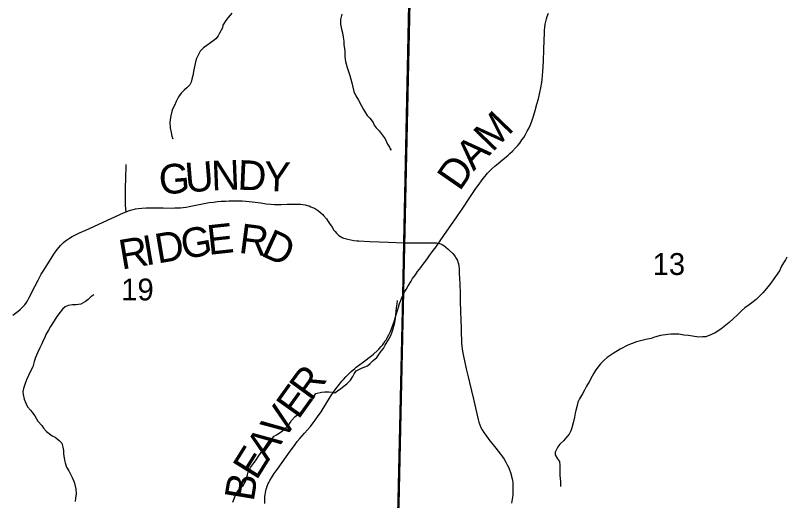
# Model space of a CAD drawing. Extents: x -7.1 to 34, y 0 to 22.
# Drawn here: x 5.914 to 7.392, y 14.742 to 15.673 of the extents above; entities that cross this region are included whole.
import ezdxf

# ---------------------------------------------------------------- set-up
doc = ezdxf.new("R2010")
doc.units = 0
for name, color, linetype in [('GM_X_County_Road', 7, 'Continuous'), ('GM_X_County_Road_Text', 7, 'Continuous'), ('GM_X_Minor_River', 7, 'Continuous'), ('GM_X_Section', 7, 'Continuous'), ('GM_X_Section_Text', 7, 'Continuous'), ('GM_X_Township_Road', 7, 'Continuous')]:
    doc.layers.add(name, color=color, linetype=linetype)

msp = doc.modelspace()

# ---------------------------------------------------------------- linework, layer by layer
at = {"layer": 'GM_X_County_Road'}
for points in [[(6.7252, 15.2358), (6.7271, 15.2386), (6.7366, 15.2523), (6.753, 15.2761), (6.7616, 15.2883), (6.7702, 15.3011), (6.7851, 15.3236), (6.7953, 15.3388), (6.8039, 15.3511), (6.8107, 15.3601), (6.8141, 15.3645), (6.8192, 15.3703), (6.8222, 15.3736), (6.8273, 15.3786), (6.833, 15.3836), (6.8391, 15.3887), (6.8475, 15.3955), (6.8583, 15.4046), (6.8617, 15.4076), (6.8668, 15.4124), (6.8728, 15.4186), (6.8768, 15.423), (6.8809, 15.4279), (6.885, 15.4338), (6.8884, 15.4388), (6.8918, 15.4444), (6.8952, 15.4504), (6.8986, 15.4573), (6.9006, 15.4617), (6.9038, 15.4699), (6.9071, 15.4795), (6.9104, 15.4902), (6.9137, 15.5024), (6.9163, 15.5126), (6.9192, 15.5249), (6.9211, 15.5339), (6.9228, 15.5439), (6.9234, 15.5497), (6.9243, 15.5575), (6.9251, 15.5654), (6.9261, 15.5848), (6.927, 15.608), (6.9281, 15.6396), (6.9284, 15.6438), (6.9288, 15.6499), (6.9295, 15.6557), (6.9307, 15.6611), (6.9319, 15.6661), (6.9334, 15.6708), (6.9355, 15.6767)], [(5.9091, 15.098), (5.9144, 15.1016), (5.9194, 15.1053), (5.9234, 15.1085), (5.9262, 15.1112), (5.9287, 15.1139), (5.9323, 15.1178), (5.9352, 15.1219), (5.9379, 15.1264), (5.94, 15.1305), (5.9515, 15.1527), (5.9576, 15.1646), (5.9639, 15.1762), (5.9685, 15.1838), (5.975, 15.1942), (5.9825, 15.2063), (5.9878, 15.2145), (5.9941, 15.2234), (5.9978, 15.2281), (6.0004, 15.2311), (6.0034, 15.2342), (6.0063, 15.237), (6.0103, 15.2403), (6.0138, 15.2429), (6.0181, 15.2456), (6.0231, 15.2485), (6.0304, 15.2523), (6.0373, 15.2555), (6.0492, 15.261), (6.0979, 15.2833), (6.1214, 15.2938), (6.1265, 15.2959), (6.1311, 15.2978), (6.1349, 15.2992), (6.1399, 15.3006), (6.1445, 15.3016), (6.1499, 15.3024), (6.1568, 15.3031), (6.1651, 15.3035), (6.1695, 15.3036), (6.1976, 15.3034), (6.2138, 15.3032), (6.2196, 15.3033), (6.2307, 15.3038), (6.236, 15.3044), (6.2413, 15.3051), (6.247, 15.306), (6.2727, 15.3114), (6.2858, 15.3137), (6.2938, 15.3147), (6.3014, 15.3156), (6.3088, 15.3162), (6.3167, 15.3166), (6.324, 15.317), (6.3305, 15.3171), (6.3429, 15.317), (6.3489, 15.3168), (6.3556, 15.3163), (6.3684, 15.3151), (6.3739, 15.3145), (6.3847, 15.313), (6.3946, 15.3115), (6.4037, 15.3105), (6.4106, 15.3101), (6.4158, 15.31), (6.4238, 15.3101), (6.4353, 15.3106), (6.4431, 15.3109), (6.4562, 15.3107), (6.4606, 15.3105), (6.4648, 15.31), (6.4694, 15.3093), (6.4734, 15.3083), (6.477, 15.3072), (6.4806, 15.3058), (6.4836, 15.3045), (6.4871, 15.3028), (6.4909, 15.3005), (6.495, 15.2976), (6.5001, 15.2935), (6.5033, 15.2907), (6.5046, 15.2892), (6.5101, 15.2826), (6.5126, 15.2792), (6.5164, 15.2735), (6.521, 15.2666), (6.5247, 15.261), (6.5269, 15.258), (6.5293, 15.2553), (6.5317, 15.253), (6.5343, 15.2508), (6.5374, 15.2487), (6.5404, 15.247), (6.5431, 15.2457), (6.5459, 15.2447), (6.5515, 15.2432), (6.5571, 15.242), (6.5627, 15.2411), (6.5687, 15.2405), (6.5723, 15.2402), (6.5936, 15.2391), (6.6292, 15.2376), (6.6589, 15.2366), (6.6647, 15.2364)], [(6.6628, 15.1472), (6.667, 15.1543), (6.6723, 15.1628), (6.6754, 15.1678), (6.6806, 15.1752), (6.685, 15.1813), (6.6911, 15.1894), (6.6956, 15.1954), (6.7006, 15.2021), (6.704, 15.2066), (6.708, 15.2121), (6.7116, 15.217), (6.7148, 15.2216), (6.7183, 15.2264), (6.7225, 15.2321), (6.7252, 15.2358)], [(6.6647, 15.2364), (6.7016, 15.2365), (6.7174, 15.2367), (6.7193, 15.2366), (6.7214, 15.2364), (6.7239, 15.236), (6.7252, 15.2358), (6.7269, 15.2354), (6.7291, 15.2347), (6.731, 15.2339), (6.7327, 15.2329), (6.7343, 15.2318), (6.7434, 15.2241), (6.746, 15.2218), (6.7522, 15.2158), (6.7544, 15.2133), (6.7569, 15.2102), (6.7585, 15.2078), (6.7598, 15.2055), (6.7611, 15.2028), (6.7623, 15.1996), (6.7633, 15.1959), (6.7638, 15.1919), (6.7643, 15.1866), (6.7647, 15.1785), (6.7656, 15.1576), (6.7664, 15.1399), (6.7668, 15.1247), (6.7673, 15.1049), (6.7678, 15.0881), (6.7683, 15.0724), (6.7687, 15.0613), (6.769, 15.0518), (6.7692, 15.044), (6.7697, 15.0386), (6.7702, 15.0333), (6.7716, 15.025), (6.7747, 15.0099), (6.7781, 14.9945), (6.7816, 14.9796), (6.7843, 14.9685), (6.7918, 14.9367), (6.8009, 14.8975), (6.8025, 14.8924), (6.8043, 14.8872), (6.8064, 14.8823), (6.8089, 14.8775), (6.8119, 14.8727), (6.8156, 14.8673), (6.8217, 14.8595), (6.8351, 14.8426), (6.8439, 14.8312), (6.8476, 14.8261), (6.8509, 14.8213), (6.854, 14.8159), (6.8566, 14.8109), (6.8589, 14.8061), (6.8601, 14.8033), (6.8634, 14.7943), (6.8644, 14.791), (6.8662, 14.7841), (6.8669, 14.7807), (6.8673, 14.7771), (6.8677, 14.7721), (6.8676, 14.7601), (6.8672, 14.7527), (6.8663, 14.7448), (6.865, 14.7371)], [(6.4972, 14.9078), (6.5, 14.9122), (6.5181, 14.9419), (6.5206, 14.9457), (6.5281, 14.9564), (6.5307, 14.9598), (6.54, 14.9713), (6.5427, 14.9744), (6.5474, 14.9793), (6.5521, 14.984), (6.5579, 14.9896), (6.5648, 14.9956), (6.5673, 14.9977), (6.574, 15.0028), (6.5814, 15.0085), (6.5971, 15.0202), (6.6004, 15.0229), (6.6083, 15.03), (6.6108, 15.0326), (6.6154, 15.0378), (6.6175, 15.0403), (6.6201, 15.044), (6.6231, 15.0483), (6.6245, 15.0505), (6.6268, 15.0545), (6.6296, 15.0598), (6.6329, 15.0667), (6.6358, 15.0736), (6.6376, 15.0787), (6.6399, 15.0854), (6.6419, 15.092), (6.6445, 15.1011), (6.6463, 15.107), (6.6483, 15.1134), (6.6505, 15.1201), (6.6526, 15.1261), (6.6539, 15.1296), (6.6553, 15.1329), (6.6579, 15.138), (6.6607, 15.1432), (6.6628, 15.1472)], [(6.392, 14.7368), (6.3922, 14.7438), (6.3925, 14.7512), (6.3927, 14.7526), (6.3934, 14.7578), (6.3948, 14.7639), (6.3952, 14.7653), (6.3967, 14.77), (6.3988, 14.7751), (6.3997, 14.7769), (6.4017, 14.7806), (6.4047, 14.7855), (6.4102, 14.7938), (6.4176, 14.8045), (6.4407, 14.8369), (6.4488, 14.8478), (6.4544, 14.8554), (6.459, 14.8611), (6.468, 14.8714), (6.4794, 14.8844), (6.485, 14.8913), (6.4889, 14.8964), (6.4966, 14.9069), (6.4972, 14.9078)]]:
    msp.add_lwpolyline(points, dxfattribs=at)
at = {"layer": 'GM_X_Minor_River'}
for points in [[(6.3217, 15.6687), (6.3172, 15.6629), (6.312, 15.6537), (6.311, 15.6487), (6.3051, 15.6388), (6.3029, 15.6334), (6.298, 15.628), (6.2928, 15.6233), (6.2879, 15.6198), (6.2808, 15.6148), (6.2744, 15.6105), (6.2681, 15.6039), (6.2637, 15.5951), (6.2607, 15.589), (6.259, 15.5802), (6.2561, 15.568), (6.2544, 15.5577), (6.2526, 15.5504), (6.2511, 15.5447), (6.2482, 15.5393), (6.243, 15.5335), (6.2374, 15.5296), (6.2318, 15.5238), (6.2269, 15.5162), (6.2222, 15.5073), (6.2192, 15.5), (6.2155, 15.4931), (6.2141, 15.4882), (6.212, 15.4798), (6.2109, 15.4729), (6.2099, 15.4676), (6.2108, 15.4573), (6.2124, 15.4482), (6.214, 15.4413), (6.2156, 15.436), (6.216, 15.4368)], [(6.3291, 15.6768), (6.3217, 15.6687)], [(6.5396, 15.6751), (6.5375, 15.6647), (6.5373, 15.6556), (6.5393, 15.6461), (6.5409, 15.6393), (6.5426, 15.6309), (6.5434, 15.6233), (6.5439, 15.6161), (6.5448, 15.6093), (6.5452, 15.6036), (6.5457, 15.5937), (6.547, 15.5842), (6.5498, 15.5728), (6.555, 15.5573), (6.559, 15.5436), (6.563, 15.527), (6.5669, 15.5186), (6.5716, 15.5103), (6.5774, 15.4994), (6.5813, 15.4922), (6.5852, 15.4858), (6.5883, 15.4805), (6.5933, 15.4757), (6.5998, 15.4674), (6.6018, 15.4621), (6.6053, 15.4572), (6.6111, 15.4512), (6.6153, 15.4459), (6.6192, 15.441), (6.6226, 15.4358), (6.6273, 15.4259), (6.6308, 15.4199), (6.6336, 15.4142), (6.6344, 15.4169)], [(7.3923, 15.2089), (7.3897, 15.2039), (7.3864, 15.1981), (7.3823, 15.1916), (7.3783, 15.1828), (7.3709, 15.172), (7.3597, 15.1566), (7.3463, 15.1404), (7.3404, 15.1339), (7.3336, 15.1277), (7.328, 15.123), (7.3202, 15.1176), (7.3123, 15.1117), (7.3059, 15.1059), (7.2981, 15.0982), (7.2817, 15.0835), (7.2663, 15.0707), (7.2554, 15.064), (7.2483, 15.0605), (7.237, 15.0565), (7.2309, 15.0561), (7.2241, 15.0556), (7.2116, 15.0573), (7.204, 15.0587), (7.1953, 15.0597), (7.1854, 15.0611), (7.1801, 15.0614), (7.1703, 15.0612), (7.1646, 15.0604), (7.1503, 15.0586), (7.1386, 15.0554), (7.1322, 15.053), (7.122, 15.0513), (7.1148, 15.0493), (7.1042, 15.0469), (7.0877, 15.0402), (7.073, 15.0327), (7.0595, 15.0245), (7.0483, 15.0163), (7.0427, 15.0117)], [(6.0644, 15.1365), (6.0588, 15.133), (6.0535, 15.1276), (6.0483, 15.1237), (6.0396, 15.119), (6.0306, 15.1177), (6.0238, 15.1176), (6.0155, 15.116), (6.0094, 15.114), (6.0046, 15.1093), (6.0001, 15.1032), (5.9934, 15.0951), (5.9886, 15.0866), (5.9812, 15.0762), (5.9775, 15.0689), (5.9727, 15.0609), (5.9705, 15.0548), (5.9676, 15.0494), (5.9647, 15.0425), (5.961, 15.0348), (5.9566, 15.0252), (5.9529, 15.0168), (5.9504, 15.0088), (5.9479, 14.9988), (5.9427, 14.9889), (5.9394, 14.982), (5.9358, 14.9735), (5.9321, 14.9647), (5.9296, 14.9571), (5.9285, 14.951), (5.929, 14.9453), (5.931, 14.9369), (5.9341, 14.929), (5.9376, 14.9222), (5.943, 14.9154), (5.9473, 14.9101), (5.9512, 14.9045), (5.957, 14.8947), (5.9647, 14.8861), (5.9678, 14.8808), (5.9739, 14.8748), (5.9846, 14.8662), (5.9907, 14.864), (5.9984, 14.8576), (6.0034, 14.852), (6.005, 14.8448), (6.0063, 14.8383), (6.0067, 14.8319), (6.0084, 14.8197), (6.0096, 14.8148), (6.012, 14.8064), (6.0163, 14.7989), (6.0206, 14.7917), (6.0233, 14.7864), (6.0253, 14.7804), (6.0276, 14.7755), (6.0301, 14.7641), (6.0306, 14.7553), (6.0295, 14.747), (6.0289, 14.7405)], [(6.331, 14.739), (6.3361, 14.7527), (6.3406, 14.7604), (6.3454, 14.767), (6.351, 14.7712), (6.3551, 14.7789), (6.359, 14.7915), (6.3605, 14.7969), (6.3645, 14.8053), (6.3705, 14.8134), (6.3757, 14.8203), (6.3816, 14.8292), (6.3875, 14.8373), (6.3924, 14.8438), (6.3961, 14.8499), (6.4001, 14.8553), (6.4054, 14.8607), (6.4098, 14.8658), (6.4147, 14.8685), (6.4218, 14.8728), (6.4293, 14.8782), (6.4372, 14.886), (6.4409, 14.891), (6.4435, 14.896), (6.4506, 14.9033), (6.4562, 14.9076), (6.461, 14.9115), (6.4674, 14.9161), (6.4734, 14.9234), (6.4793, 14.9296), (6.4823, 14.9354), (6.486, 14.9419), (6.49, 14.9473), (6.5006, 14.9501), (6.5074, 14.9506), (6.515, 14.9507), (6.5214, 14.9501), (6.5264, 14.949), (6.5312, 14.9529), (6.5376, 14.9568), (6.5492, 14.9661), (6.5563, 14.973), (6.5611, 14.98), (6.5637, 14.985), (6.5674, 14.9911), (6.5776, 14.9962), (6.5888, 15.0006), (6.5941, 15.0052), (6.6001, 15.011), (6.6068, 15.0164), (6.6105, 15.0226), (6.6149, 15.0284), (6.6194, 15.0338), (6.6231, 15.0403), (6.6301, 15.0514), (6.6331, 15.0576), (6.6353, 15.0637), (6.6378, 15.0698), (6.641, 15.0836), (6.6428, 15.0916), (6.6435, 15.0977), (6.6441, 15.1046), (6.6448, 15.1118), (6.6458, 15.1194), (6.6465, 15.1259)], [(7.0427, 15.0117), (7.0356, 15.0047), (7.0263, 14.9928), (7.0226, 14.9866), (7.0196, 14.9805), (7.0137, 14.9698), (7.0089, 14.9613), (7.0049, 14.954), (7.0008, 14.9471), (6.9953, 14.9371), (6.9923, 14.9306), (6.9905, 14.9245), (6.988, 14.9149), (6.9866, 14.91), (6.9856, 14.9023), (6.9831, 14.8913), (6.9806, 14.8817), (6.9788, 14.8756), (6.9754, 14.8698), (6.9706, 14.8641), (6.9646, 14.8567), (6.9575, 14.8502), (6.9535, 14.8451), (6.9483, 14.8348), (6.9488, 14.8298), (6.953, 14.8223), (6.9569, 14.817), (6.9574, 14.8094), (6.9572, 14.7957), (6.9577, 14.7904), (6.959, 14.779), (6.9586, 14.7691)]]:
    msp.add_lwpolyline(points, dxfattribs=at)
at = {"layer": 'GM_X_Section'}
for points in [[(6.6705, 15.7268), (6.6482, 14.7054), (5.6272, 14.7254), (5.6569, 15.7356)], [(7.6901, 15.7003), (7.6641, 14.6933), (6.6482, 14.7054), (6.6705, 15.7268)]]:
    msp.add_lwpolyline(points, close=True, dxfattribs=at)
at = {"layer": 'GM_X_Township_Road'}
for points in [[(2.1, 17.7253), (2.1, 14.1), (6.633, 14.1), (6.6565, 15.1357), (6.6586, 15.2372), (6.6748, 15.9993), (6.6822, 16.3488), (6.7058, 17.2839), (6.7118, 17.7486)], [(6.1265, 15.2959), (6.1258, 15.3017), (6.1252, 15.3086), (6.125, 15.3184), (6.1254, 15.3438), (6.1258, 15.3584), (6.1268, 15.3865)]]:
    msp.add_lwpolyline(points, dxfattribs=at)
msp.add_lwpolyline([(6.633, 14.1), (8.9, 14.1), (8.9, 17.7079), (8.6668, 17.7136), (8.4472, 17.7189), (7.7202, 17.7285), (6.7118, 17.7486), (6.7058, 17.2839), (6.6822, 16.3488), (6.6748, 15.9993), (6.6586, 15.2372), (6.6565, 15.1357)], close=True, dxfattribs=at)

# ---------------------------------------------------------------- texts
at = {"layer": 'GM_X_County_Road_Text'}
for s, rotation, p in [('M', 46.0022, (6.8282, 15.409)), ('A', 45.1442, (6.7922, 15.3729)), ('D', 55.2834, (6.7655, 15.3339)), ('G', 4.6021, (6.1914, 15.3288)), ('U', 4.5546, (6.2413, 15.3328)), ('N', 2.2592, (6.2905, 15.3368)), ('D', 357.3872, (6.3392, 15.3387)), ('Y', 357.1392, (6.3891, 15.3364)), ('G', 9.5815, (6.2362, 15.205)), ('E', 6.2006, (6.2846, 15.2132)), ('R', 352.6029, (6.3408, 15.2176)), ('I', 9.6304, (6.1639, 15.1928)), ('D', 9.6222, (6.1869, 15.1967)), ('D', 335.4343, (6.3827, 15.2128)), ('R', 9.6311, (6.1179, 15.185)), ('R', 53.8108, (6.481, 14.9306)), ('E', 54.3353, (6.4564, 14.8962)), ('V', 54.3374, (6.4272, 14.8555)), ('A', 54.395, (6.3981, 14.8149)), ('E', 58.1182, (6.3762, 14.7796)), ('B', 80.6814, (6.3707, 14.7391))]:
    msp.add_text(s, height=0.0568, rotation=rotation, dxfattribs=at).set_placement(p)
at = {"layer": 'GM_X_Section_Text'}
for s, p in [('13', (7.1353, 15.1749)), ('19', (6.117, 15.1261))]:
    msp.add_text(s, height=0.04186, rotation=0, dxfattribs=at).set_placement(p)

doc.saveas('drawing.dxf')
